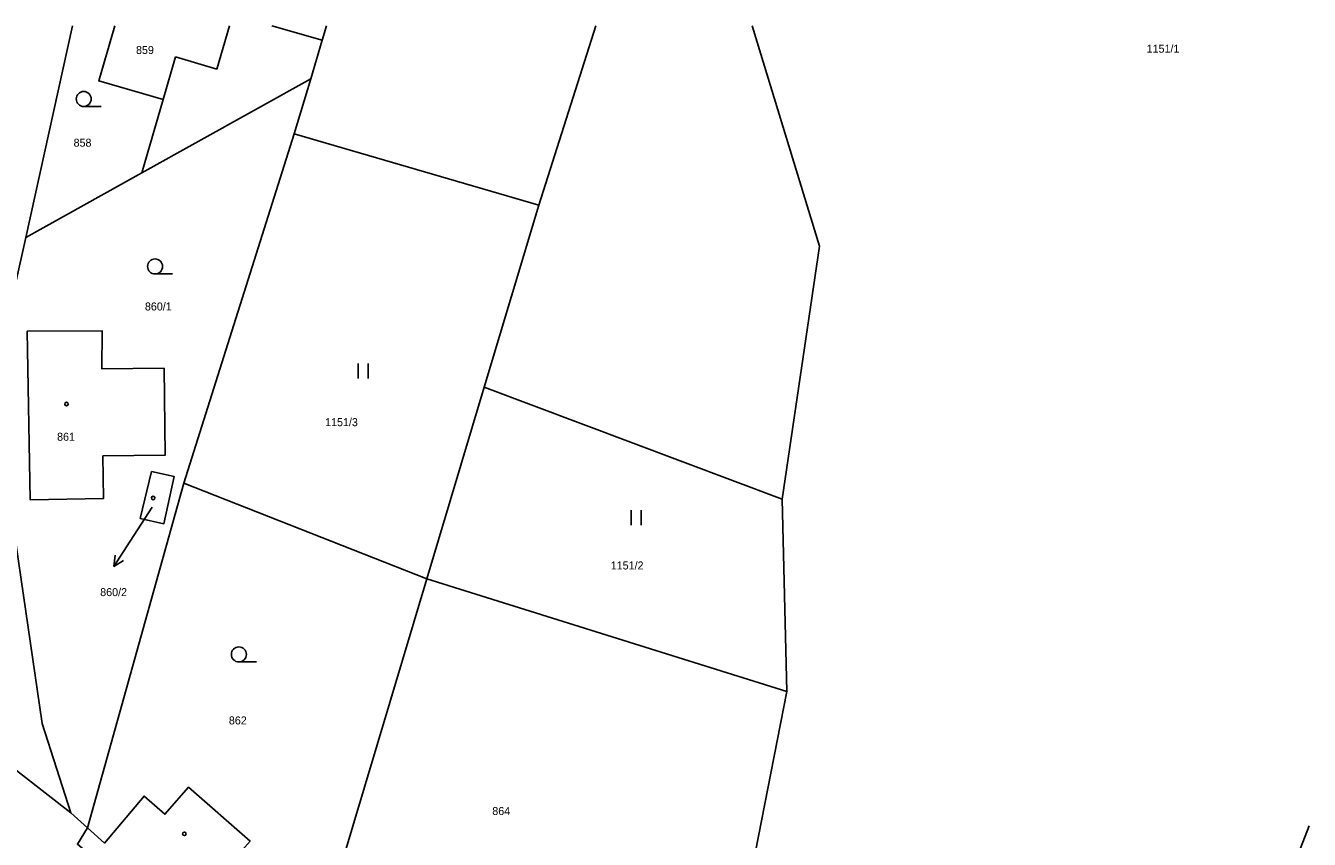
# Model space of a CAD drawing. Extents: x -719706 to -718922, y -950351 to -949651.
# Drawn here: x -719050.5 to -718922.2, y -949732.4 to -949651 of the extents above; entities that cross this region are included whole.
import ezdxf

# ---------------------------------------------------------------- set-up
doc = ezdxf.new("R2010")
doc.units = 0
doc.layers.add('Doplňující texty', color=7, linetype='Continuous')

msp = doc.modelspace()

# ---------------------------------------------------------------- linework, layer by layer
at = {"layer": 'Doplňující texty'}
for p, q in [((-719050.48, -949672.23), (-719045.84, -949651.04)), ((-719031.4, -949655.38), (-719030.13, -949651.04)), ((-719020.43, -949651.04), (-719020.87, -949652.5)), ((-718999.23, -949669), (-718993.51, -949651.04)), ((-719020.87, -949652.5), (-719022.01, -949656.34)), ((-719036.76, -949658.43), (-719035.53, -949654.17)), ((-719035.53, -949654.17), (-719031.4, -949655.38)), ((-719038.9, -949665.77), (-719022.01, -949656.34)), ((-719022.01, -949656.34), (-719023.66, -949661.87)), ((-719044.71, -949659.12), (-719042.96, -949659.12)), ((-719023.66, -949661.87), (-719034.7, -949696.79)), ((-719023.66, -949661.87), (-718999.23, -949669)), ((-719050.48, -949672.23), (-719038.9, -949665.77)), ((-719004.68, -949687.2), (-718999.23, -949669)), ((-719037.58, -949675.87), (-719035.83, -949675.87)), ((-719017.27, -949686.32), (-719017.27, -949684.82)), ((-719016.27, -949686.32), (-719016.27, -949684.82)), ((-719004.68, -949687.2), (-719010.42, -949706.36)), ((-718974.9, -949698.4), (-719004.68, -949687.2)), ((-719034.7, -949696.79), (-719044.34, -949731.26)), ((-719010.42, -949706.36), (-719034.7, -949696.79)), ((-718974.9, -949698.4), (-718974.43, -949717.63)), ((-719037.88, -949699.2), (-719040.06, -949702.59)), ((-718989.99, -949700.99), (-718989.99, -949699.49)), ((-718988.99, -949700.99), (-718988.99, -949699.49)), ((-719040.06, -949702.59), (-719041.69, -949705.11)), ((-719041.69, -949705.11), (-719041.57, -949703.99)), ((-719041.69, -949705.11), (-719040.73, -949704.54)), ((-719024.28, -949752.64), (-719010.42, -949706.36)), ((-718974.43, -949717.63), (-719010.42, -949706.36)), ((-719029.2, -949714.67), (-719027.45, -949714.67)), ((-718979.78, -949744.95), (-718974.43, -949717.63)), ((-719045.99, -949729.75), (-719057.21, -949721.03)), ((-719044.34, -949731.26), (-719045.99, -949729.75))]:
    msp.add_line(p, q, dxfattribs=at)
for points in [[(-719038.9, -949665.77), (-719036.76, -949658.43), (-719043.2, -949656.56), (-719041.59, -949651.04)], [(-719025.9, -949651.04), (-719020.87, -949652.5)], [(-718977.89, -949651.04), (-718971.18, -949673.09), (-718974.9, -949698.4)], [(-719045.99, -949729.75), (-719048.86, -949720.82), (-719053.39, -949689.97), (-719052.49, -949681.2), (-719050.48, -949672.23)], [(-719042.79, -949694.07), (-719036.58, -949694), (-719036.68, -949685.3), (-719042.89, -949685.37), (-719042.88, -949681.54), (-719050.37, -949681.6), (-719050.07, -949698.45), (-719042.72, -949698.32), (-719042.79, -949694.07)], [(-719039.08, -949700.31), (-719037.93, -949695.64), (-719035.66, -949696.14), (-719036.7, -949700.85), (-719039.08, -949700.31)], [(-719044.34, -949731.26), (-719042.64, -949732.79), (-719038.67, -949728.09), (-719036.59, -949729.91), (-719034.23, -949727.21), (-719028.08, -949732.59), (-719029.18, -949733.84), (-719026.94, -949735.79), (-719028.37, -949737.43), (-719027.13, -949738.7), (-719030.58, -949742.76), (-719032.55, -949741.04), (-719034.08, -949742.47)], [(-719034.08, -949742.47), (-719045.34, -949732.9), (-719044.34, -949731.26)], [(-718922.21, -949731.05), (-718944.1, -949787.5), (-718969.91, -949799.6), (-718985.79, -949797.2)]]:
    msp.add_lwpolyline(points, dxfattribs=at)
for centre, radius in [((-719044.71, -949658.37), 0.75), ((-719037.58, -949675.12), 0.75), ((-719046.43, -949688.88), 0.175), ((-719037.77, -949698.27), 0.175), ((-719029.2, -949713.92), 0.75), ((-719034.65, -949731.86), 0.175)]:
    msp.add_circle(centre, radius, dxfattribs=at)

# ---------------------------------------------------------------- texts
for s, p in [('859', (-719039.48, -949653.87)), ('1151/1', (-718938.47, -949653.74)), ('858', (-719045.72, -949663.14)), ('860/1', (-719038.59, -949679.52)), ('1151/3', (-719020.58, -949691.09)), ('861', (-719047.37, -949692.55)), ('1151/2', (-718992.03, -949705.42)), ('860/2', (-719043.06, -949708.09)), ('862', (-719030.2, -949720.92)), ('864', (-719003.87, -949729.98))]:
    msp.add_text(s, height=0.8, dxfattribs=at).set_placement(p)

doc.saveas('drawing.dxf')
